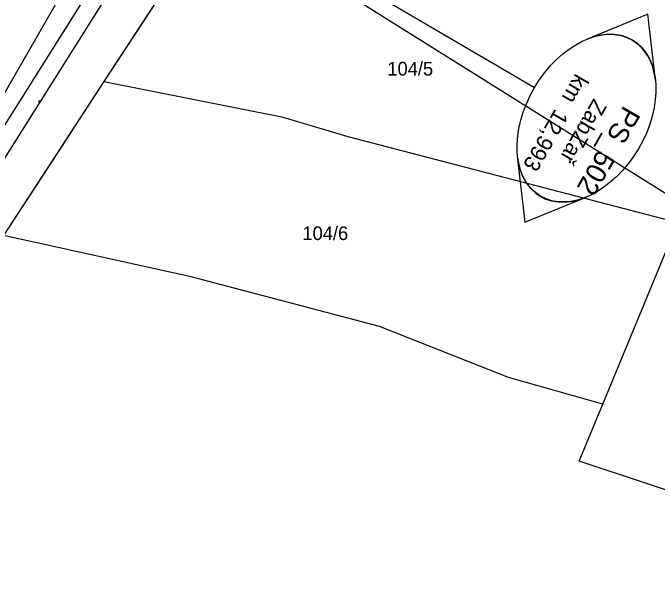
# Model space of a CAD drawing. Extents: x -746176 to -739709, y -1128407 to -1124482.
# Drawn here: x -743194.3 to -743114.2, y -1127186.5 to -1127113.5 of the extents above; entities that cross this region are included whole.
import ezdxf

# ---------------------------------------------------------------- set-up
doc = ezdxf.new("R2010")
doc.units = 0
for name, color, linetype in [('Default', 7, 'Continuous'), ('Vrstva 18', 7, 'Continuous'), ('Vrstva 29', 7, 'Continuous'), ('Vrstva 30', 7, 'Continuous'), ('Vrstva 32', 7, 'Continuous'), ('Vrstva 33', 7, 'Continuous'), ('Vrstva 35', 7, 'Continuous'), ('Vrstva 42', 7, 'Continuous'), ('Vrstva 45', 7, 'Continuous'), ('Vrstva 5', 7, 'Continuous')]:
    doc.layers.add(name, color=color, linetype=linetype)

# ---------------------------------------------------------------- blocks, each defined once
blk = doc.blocks.new('AeccTickCircle')
at = {"layer": 'Default'}
blk.add_circle((0, 0), 5, dxfattribs=at)

msp = doc.modelspace()

# ---------------------------------------------------------------- linework, layer by layer
at = {"layer": 'Vrstva 18'}
msp.add_lwpolyline([(-743072.487, -1126932.751), (-743098.647, -1126974.146), (-743125.94, -1127017.384), (-743152.604, -1127059.608), (-743175.023, -1127095.116), (-743199.163, -1127133.346), (-743215.971, -1127159.941), (-743232.818, -1127186.515), (-743247.456, -1127209.811), (-743254.52, -1127221.639), (-743261.299, -1127233.691), (-743264.155, -1127239.195), (-743264.862, -1127241.108), (-743267.337, -1127245.816), (-743268.289, -1127247.159), (-743271.711, -1127253.75), (-743281.122, -1127274.196), (-743291.923, -1127301.42), (-743296.724, -1127315.222), (-743301.116, -1127329.128), (-743306.787, -1127349.506)], dxfattribs=at)
at = {"layer": 'Vrstva 29'}
msp.add_lwpolyline([(-743178.712, -1127105.086), (-743197.526, -1127134.888)], dxfattribs=at)
at = {"layer": 'Vrstva 30'}
for p, q in [((-743129.509, -1127122.8), (-743175.485, -1127095.847)), ((-743109.419, -1127138.306), (-743174.121, -1127097.814))]:
    msp.add_line(p, q, dxfattribs=at)
at = {"layer": 'Vrstva 33'}
for p, q in [((-743171.62, -1127104.6), (-743183.01, -1127122.02)), ((-743183.01, -1127122.02), (-743195.51, -1127141.13)), ((-743121.01, -1127162.08), (-743111.68, -1127139.51))]:
    msp.add_line(p, q, dxfattribs=at)
for points in [[(-743280.26, -1127263.68), (-743264.54, -1127233.06), (-743246.95, -1127204.21), (-743235.54, -1127186.77), (-743205.03, -1127140.21), (-743183.34, -1127102.57)], [(-743183.01, -1127122.02), (-743160.92, -1127126.4), (-743152.69, -1127128.83), (-743111.68, -1127139.51)], [(-743121.01, -1127162.08), (-743132.72, -1127158.77), (-743148.75, -1127152.44), (-743172.16, -1127146.26), (-743195.51, -1127141.13)], [(-743098.58, -1127177.58), (-743123.94, -1127169.17), (-743121.01, -1127162.08)]]:
    msp.add_lwpolyline(points, dxfattribs=at)
at = {"layer": 'Vrstva 35'}
for p, q in [((-743115.402, -1127113.652), (-743123.035, -1127116.793)), ((-743115.402, -1127113.652), (-743123.035, -1127116.793)), ((-743114.462, -1127121.853), (-743115.402, -1127113.652)), ((-743114.462, -1127121.853), (-743115.402, -1127113.652)), ((-743131.631, -1127131.305), (-743130.691, -1127139.506)), ((-743131.631, -1127131.305), (-743130.691, -1127139.506)), ((-743130.691, -1127139.506), (-743123.058, -1127136.365)), ((-743130.691, -1127139.506), (-743123.058, -1127136.365))]:
    msp.add_line(p, q, dxfattribs=at)
msp.add_ellipse((-743123.025, -1127126.57), major_axis=(-5.718, -9.689), ratio=0.666667, dxfattribs=at)
for centre, major_axis in [((-743123.025, -1127126.57), (5.719, 9.69)), ((-743123.068, -1127126.587), (-5.719, -9.69))]:
    msp.add_ellipse(centre, major_axis=major_axis, ratio=0.666473, start_param=5.557317, end_param=7.009053, dxfattribs=at)
at = {"layer": 'Vrstva 5'}
msp.add_lwpolyline([(-743235.54, -1127186.77), (-743220.285, -1127163.49), (-743205.03, -1127140.21), (-743194.185, -1127121.39), (-743183.34, -1127102.57), (-743177.48, -1127103.585), (-743171.62, -1127104.6), (-743177.315, -1127113.31), (-743183.01, -1127122.02), (-743189.26, -1127131.575), (-743195.51, -1127141.13), (-743203.92, -1127154.43), (-743209.935, -1127163.585), (-743215.95, -1127172.74), (-743213.155, -1127173.38), (-743210.36, -1127174.02), (-743223.82, -1127189.755)], dxfattribs=at)

# ---------------------------------------------------------------- block references
at = {"layer": 'Vrstva 45', "xscale": 0.024999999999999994, "yscale": 0.024999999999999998, "rotation": 57.71650678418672}
msp.add_blockref('AeccTickCircle', (-743190.973, -1127124.502), dxfattribs=at)

# ---------------------------------------------------------------- texts
at = {"layer": 'Vrstva 32'}
for s, height, p in [('km  12,993', 2, (-743124.39, -1127120.923)), ('ZabZař', 2, (-743122.122, -1127124.018)), ('PS_502', 2.5, (-743118.382, -1127124.89))]:
    msp.add_text(s, height=height, rotation=240.12167, dxfattribs=at).set_placement(p)
at = {"layer": 'Vrstva 42'}
for s, p in [('104/5', (-743147.78, -1127121.28)), ('104/6', (-743158.34, -1127141.71))]:
    msp.add_text(s, height=1.7, dxfattribs=at).set_placement(p)

doc.saveas('drawing.dxf')
